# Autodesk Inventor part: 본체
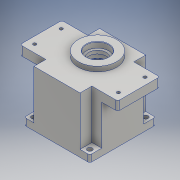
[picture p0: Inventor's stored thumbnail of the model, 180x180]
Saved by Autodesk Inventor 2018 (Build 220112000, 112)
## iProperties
Created: 2020-07
Part Number: 본체
Material: 알루미늄 6061
Document SubType Name: Modeling
Designer: Admin
Density: 2.7 g/cm^3
Appearance: 알루미늄 - 평지
Mass: 876.486 g
Surface Area: 793.573 cm^2
Volume: 324.624 cm^3
Author: Admin
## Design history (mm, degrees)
sketch "스케치1"
  geometry: L1 (-65.8, 0)-(65.8, 0) reference; L2 (0, -65.8)-(0, 65.8) reference; L3 (47, -47)-(-47, -47); L4 (-47, -47)-(-47, 47); L5 (-47, 47)-(47, 47); L6 (47, 47)-(47, -47); L7 (47, -47)-(-47, 47); L8 (-47, -47)-(47, 47); 1 further point
  constraints: 12 end point, 2 midpoint, 2 parallel, 1 horizontal, 1 perpendicular
  dimensions: "d0" = 94 distance of L4.end L5.end; "d1" = 94 distance of L3.end L4.end
extrude "돌출1" new body sketch "스케치1" distance "d2" = 80; taper "d3" = 0 deg
sketch "스케치2"
  geometry: L1 (-98, 0)-(98, 0) reference; L2 (0, -65.8)-(0, 65.8) reference; L3 (70, -30)-(-70, -30); L4 (-70, -30)-(-70, 30); L5 (-70, 30)-(70, 30); L6 (70, 30)-(70, -30); L7 (70, -30)-(-70, 30); L8 (-70, -30)-(70, 30); 1 further point
  constraints: 12 end point, 2 midpoint, 2 parallel, 1 horizontal, 1 perpendicular
  dimensions: "d4" = 140 distance of L4.end L5.end; "d5" = 60 distance of L3.end L4.end
extrude "돌출2" join sketch "스케치2" distance "d6" = 13; taper "d7" = 0 deg
sketch "스케치3"
  geometry: L1 (-47, 47)-(-47, 30) reference; L2 (-47, 47)-(-33, 47); L3 (-33, 47)-(-33, 30); L4 (-33, 30)-(-47, 30); L5 (-47, 30)-(-47, 47); L6 (-98, 0)-(98, 0) reference; L7 (0, -65.8)-(0, 65.8) reference; L8 (47, 47)-(47, 30); L9 (47, 47)-(33, 47); L10 (33, 47)-(33, 30); L11 (33, 30)-(47, 30); L12 (47, 30)-(47, 47); L13 (-47, -47)-(-47, -30); L14 (-47, -47)-(-33, -47); L15 (-33, -47)-(-33, -30); L16 (-33, -30)-(-47, -30); L17 (-47, -30)-(-47, -47); L18 (47, -47)-(47, -30); L19 (47, -47)-(33, -47); L20 (33, -47)-(33, -30); L21 (33, -30)-(47, -30); L22 (47, -30)-(47, -47); 1 further point
  constraints: 38 end point, 15 symmetric about line, 2 parallel, 1 horizontal, 1 perpendicular
  dimensions: "d8" = 33 distance between parallel lines of L7 L3; "d9" = 30 distance between parallel lines of L6 L4
extrude "돌출3" cut sketch "스케치3" distance "d10" = 70; taper "d11" = 0 deg
sketch "스케치4"
  geometry: L1 (-98, 0)-(98, 0) reference; L2 (0, -65.8)-(0, 65.8) reference; C1 r 27.5 at (0, 11); 1 further point
  constraints: 1 centre point, 1 point on line
  dimensions: "d12" = 55 diameter of C1; "d13" = 11 distance from line of L1 C1.centre
extrude "돌출4" join sketch "스케치4" distance "d14" = 7; taper "d15" = 0 deg
sketch "스케치5"
  geometry: C1 r 16 at (0, 0); C2 r 27.5 at (0, 0) reference; 1 further point
  constraints: 1 centre point, 1 concentric
  dimensions: "d16" = 32 diameter of C1
extrude "돌출5" cut sketch "스케치5" distance "d17" = 8.3; taper "d18" = 0 deg
sketch "스케치6"
  geometry: C1 r 12.5 at (0, 0); C2 r 16 at (0, 0) reference; 1 further point
  constraints: 1 centre point, 1 concentric
  dimensions: "d19" = 25 diameter of C1
extrude "돌출6" cut sketch "스케치6" distance "d20" = 4.7; taper "d21" = 0 deg
chamfer "모따기1" distance "d22" = 0.8; stored, may be unused: second distance "d23" = 2, angle "d24" = 30 deg
fillet "모깎기1" dims "d25" = 3
fillet "모깎기2" dims "d26" = 3
sketch "스케치7"
  geometry: L1 (65.8, 0)-(-65.8, 0) reference; L2 (0, -65.8)-(0, 65.8) reference; L3 (-40, -40)-(40, -40); L4 (40, -40)-(40, 40); L5 (40, 40)-(-40, 40); L6 (-40, 40)-(-40, -40); L7 (-40, -40)-(40, 40); L8 (40, -40)-(-40, 40); 5 further points
  constraints: 12 end point, 4 coincident, 2 midpoint, 2 parallel, 1 horizontal, 1 perpendicular
  dimensions: "d27" = 80 distance of L4.end L5.end; "d28" = 80 distance of L3.end L4.end
hole "구멍1" sketch "스케치7" at (40, 40), (-40, 40), (-40, -40), (40, -40) diameter "d29" = 7; stored, may be unused: countersink angle "d33" = 90 deg, drill point angle "d35" = 118 deg; dims "d30" = 6, "d31" = 4, "d32" = 2, "d34" = 8
sketch "스케치9"
  geometry: L1 (0, -65.8)-(0, 65.8) reference; L2 (98, 0)-(-98, 0) reference; L3 (-60, -19)-(60, -19); L4 (60, -19)-(60, 19); L5 (60, 19)-(-60, 19); L6 (-60, 19)-(-60, -19); L7 (-60, -19)-(60, 19); L8 (60, -19)-(-60, 19); 5 further points
  constraints: 12 end point, 4 coincident, 2 midpoint, 2 parallel, 1 horizontal, 1 perpendicular
  dimensions: "d38" = 38 distance of L3.end L4.end; "d39" = 120 distance of L4.end L5.end
hole "구멍2" sketch "스케치9" at (60, 19), (60, -19), (-60, -19), (-60, 19) diameter "d40" = 4.5; stored, may be unused: countersink angle "d44" = 90 deg, drill point angle "d46" = 118 deg; dims "d41" = 6, "d42" = 10, "d43" = 5, "d45" = 8
sketch "스케치10"
  geometry: L1 (65.8, 0)-(-65.8, 0) reference; L2 (0, -65.8)-(0, 65.8) reference; C1 r 43 at (0, 0); 1 further point
  constraints: 1 centre point, 1 coincident
  dimensions: "d47" = 86 diameter of C1
extrude "돌출7" cut sketch "스케치10" distance "d48" = 9; taper "d49" = 0 deg
sketch "스케치11"
  geometry: L1 (98, 0)-(-98, 0) reference; L2 (0, -65.8)-(0, 65.8) reference; C1 r 40 at (0, 0); 1 further point
  constraints: 1 centre point, 1 coincident
  dimensions: "d50" = 80 diameter of C1
extrude "돌출8" cut sketch "스케치11" distance "d51" = 62; taper "d52" = 0 deg
sketch "스케치12"
  geometry: L1 (-98, -11)-(98, -11) reference; L2 (0, -76.8)-(0, 54.8) reference; C1 r 17.5 at (0, 0); 1 further point
  constraints: 1 centre point, 1 point on line
  dimensions: "d53" = 35 diameter of C1; "d54" = 11 distance from line of L1 C1.centre
extrude "돌출9" cut sketch "스케치12" distance "d55" = 10; taper "d56" = 0 deg
sketch "스케치13"
  geometry: L1 (98, 0)-(-98, 0) reference; L2 (0, -65.8)-(0, 65.8) reference; C1 r 9.5 at (0, -20); 1 further point
  constraints: 1 centre point, 1 point on line
  dimensions: "d57" = 19 diameter of C1; "d58" = 20 distance from line of L1 C1.centre
extrude "돌출10" cut sketch "스케치13" distance "d59" = 3; taper "d60" = 0 deg
fillet "모깎기4" dims "d74" = 3
sketch "스케치17"
  geometry: L1 (98, 0)-(-98, 0) reference; L2 (0, -65.8)-(0, 65.8) reference; C1 r 17.5 at (0, 11) reference; C2 r 11 at (0, -20); A1 r 21 centre (0, 11) between (8.978, -7.984) and (-8.978, -7.984); A2 r 15 centre (0, -20) between (-8.978, -7.984) and (8.978, -7.984); 1 further point
  constraints: 4 point on circle, 3 centre point, 2 point on line, 1 coincident
  dimensions: "d75" = 42 diameter of A1; "d76" = 11 distance from line of L1 A1.centre; "d77" = 30 diameter of A2; "d78" = 20 distance from line of L1 A2.centre; "d79" = 22 diameter of C2
extrude "돌출12" join sketch "스케치17" distance "d80" = 7; taper "d81" = 0 deg
chamfer "모따기3" distance "d82" = 1; stored, may be unused: second distance "d83" = 2, angle "d84" = 45 deg
fillet "모깎기5" dims "d85" = 3
sketch "스케치18" dims "d87" = 72
  geometry: L1 (98, 0)-(-98, 0) reference; L2 (0, -65.8)-(0, 65.8) reference; L3 (-36, 4)-(-41.547, 4); L4 (-41.547, 4)-(-41.547, -4); L5 (-41.547, -4)-(-36, -4); L6 (36, 4)-(41.547, 4); L7 (41.547, 4)-(41.547, -4); L8 (41.547, -4)-(36, -4); A1 r 4 centre (-36, 0) between (-36, -4) and (-36, 4); A2 r 4 centre (36, 0) between (36, 4) and (36, -4); 2 further points
  constraints: 12 end point, 5 symmetric about line, 4 point on circle, 2 centre point, 2 perpendicular, 2 tangent, 1 coincident, 1 horizontal, 1 horizontal alignment, 1 point on line, 3 other
  dimensions: "d88" = 8 diameter of A1; "d89" = 5.54683 distance of L3.start L3.end
extrude "돌출13" join sketch "스케치18" distance "d90" = 62; taper "d91" = 0 deg
fillet "모깎기6" dims "d92" = 3
sketch "스케치19"
  geometry: L1 (98, 0)-(-98, 0) reference; L2 (0, -65.8)-(0, 65.8) reference; A1 r 36 centre (0, 0) between (-36, 0) and (36, 0); 1 further point
  constraints: 2 point on circle, 2 point on line, 1 centre point, 1 coincident
  dimensions: "d93" = 72 diameter of A1
hole "구멍3" sketch "스케치19" at (-36, 0), (36, 0) diameter "d94" = 3.242; stored, may be unused: countersink angle "d98" = 90 deg, drill point angle "d100" = 118 deg; dims "d95" = 7, "d96" = 4, "d97" = 2, "d99" = 9
chamfer "모따기4" distance "d101" = 1; stored, may be unused: second distance "d102" = 2, angle "d103" = 45 deg
sketch "스케치20"
  geometry: L1 (25.177, 7.886)-(25.177, 72.114); L2 (25.177, 72.114)-(40.823, 72.114); L3 (40.823, 72.114)-(40.823, 7.886); L4 (40.823, 7.886)-(25.177, 7.886); L5 (40.823, 7.886)-(25.177, 72.114); L6 (40.823, 72.114)-(25.177, 7.886); L7 (-11, 80)-(77, 80) reference; L8 (33, 97.4)-(33, -24.4) reference; 2 further points
  constraints: 4 end point, 1 midpoint, 3 other
  dimensions: "d104" = 40 distance from line of L7 point (33, 40)
feature "엠보싱1" sketch "스케치20" dims "d105" = 0.5, "d106" = 0
node "솔리드1"
